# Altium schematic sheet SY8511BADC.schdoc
size 127 x 101 mm
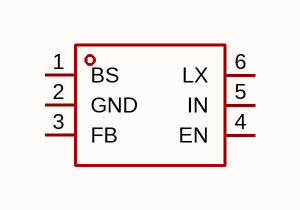
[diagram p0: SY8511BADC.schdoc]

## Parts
U?  sy8511badc  [TSOT-23-6_L2.9-W1.6-P0.95-LS2.8-BR]  (value not drawn)

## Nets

Not connected (* = marked no-connect by the designer): U? 1(BS) 2(GND) 3(FB) 4(EN) 5(IN) 6(LX)

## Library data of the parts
U? = sy8511badc: 功能类型:降压型;工作电压:4.5V~100V;输出电压:-;输出电流:1.2A;输出类型:可调;; Manufacturer: Silergy(矽力杰); AddInBom: yes; ModelId: 2c4039b5b88644c1bda4b4ba9e971667; ModelName: TSOT-23-6_L2.9-W1.6-H1.1-LS2.8-P0.95; ModelTransform: 110.45568,114.173,0,180,0,0,-0.005,-0.0005,0; Function: 降压型; Output Current: 1.2A; Frequency - Switching: 200kHz; Synchronous Rectifier: 否; Number of Outputs: 1; Topology: 降压式; Quiescent Current: 150uA; Switch tube (built-in/external): 内置; Output Type: 可调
